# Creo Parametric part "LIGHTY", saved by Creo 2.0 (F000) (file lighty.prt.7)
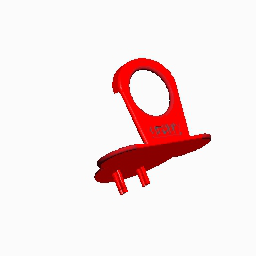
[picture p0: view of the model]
Units: millimeter Kilogram Sec (mmKs); MM, KILOGRAM, SECS
Materials in the file: ACIER

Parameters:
  PTC_COMMON_NAME = "lighty.prt"
  PTC_MATERIAL_NAME = "ACIER"
  MFG_WP_MATERIAL = "ACIER"
  PRO_UNIT_SYS = "Custom"
  NORME = "ACIER"

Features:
  1. coordinate system
  2. datum plane "DROITE"
  3. datum plane "DESSUS"
  4. datum plane "FACE"
  5. protrusion "Section 1"
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
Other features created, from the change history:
  round "Arrondi 1" (3 times)
  round "Arrondi 2" (4 times)
  round "Arrondi 3" (3 times)
  round "Arrondi 4"
  sketch "Esquisse 1"
  extrusion "Extrusion 5"
  datum plane "DTM3"
  mirror "Symetrie 1" (2 times)
  datum plane "DTM4" (2 times)
  extrusion "Extrusion 6"
  sketch "Esquisse 2"
  extrusion "Extrusion 7"
  sketch "Esquisse 3"
  extrusion "Extrusion 8"
  sketch "Esquisse 4"
  extrusion "Extrusion 9"
  extrusion "Extrusion 10"
  round "Arrondi 5"
  round "Arrondi 6"
  extruded cut "Extrusion 11"
  extruded cut "Extrusion 12"

Other named items: DEFAUT, DESSOUS, GAUCHE, ISO, ANNOT_LAYER_STATE0001, ANNOT_LAYER_STATE0002, ANNOT_LAYER_STATE0003, ANNOT_LAYER_STATE0004, ANNOT_LAYER_STATE0005, ANNOT_LAYER_STATE0006, ANNOT_LAYER_STATE0007

Layers: COTES_360, COT_PARAM, FCT_COURBES, FCT_NOGEOM, FCT_PROTRUSIONS, FONCTIONS, REF_AXES, REF_DEF_PLANS, REF_PLANS, REF_POINTS, REF_REPERES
